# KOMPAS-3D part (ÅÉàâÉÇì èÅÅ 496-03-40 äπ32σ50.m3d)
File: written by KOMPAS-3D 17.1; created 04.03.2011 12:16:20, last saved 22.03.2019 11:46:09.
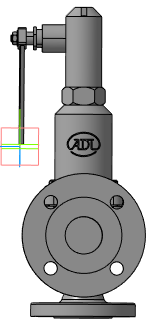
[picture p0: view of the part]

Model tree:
1. Плоскость XY
2. Плоскость ZX
3. Плоскость ZY
4. Ось X
5. Ось Y
6. Ось Z
7. Начало координат
8. Операция без истории:2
